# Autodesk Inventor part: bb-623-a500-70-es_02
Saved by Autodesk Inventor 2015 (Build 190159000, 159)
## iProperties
Created: 2022-04
Part Number: bb-623-a500-70-es_02
Checked By: TraceParts S.A.
Material: Generic
Catalog Web Link: www.traceparts.com
Document SubType Name: Modeling
Designer: TraceParts
Density: 1 g/cm^3
Appearance: Default
Company: TraceParts S.A.
Author: TraceParts
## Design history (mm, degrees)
feature "bb-623-a500-70-es_02.ipt"
body "Solid1"
